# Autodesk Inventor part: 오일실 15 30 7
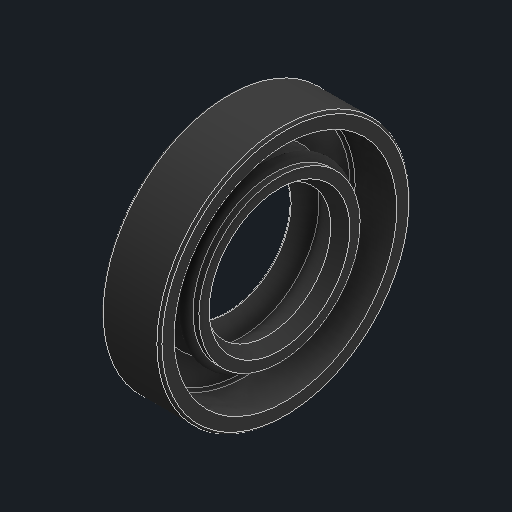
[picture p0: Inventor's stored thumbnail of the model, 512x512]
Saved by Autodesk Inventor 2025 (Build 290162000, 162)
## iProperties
Created: 2025-08
Part Number: 오일실 15 30 7
Material: 고무
Description: 오일-실
Document SubType Name: Modeling
Designer: infra027
Density: 0.93 g/cm^3
Appearance: 기본값
Author: jhkim
Sending System: Autodesk Inventor 2026
Preprocessor: ST-DEVELOPER v20.1
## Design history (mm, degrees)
feature "Solid1"
node "솔리드1"
